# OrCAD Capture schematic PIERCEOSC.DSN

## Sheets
1 PAGE1: size A
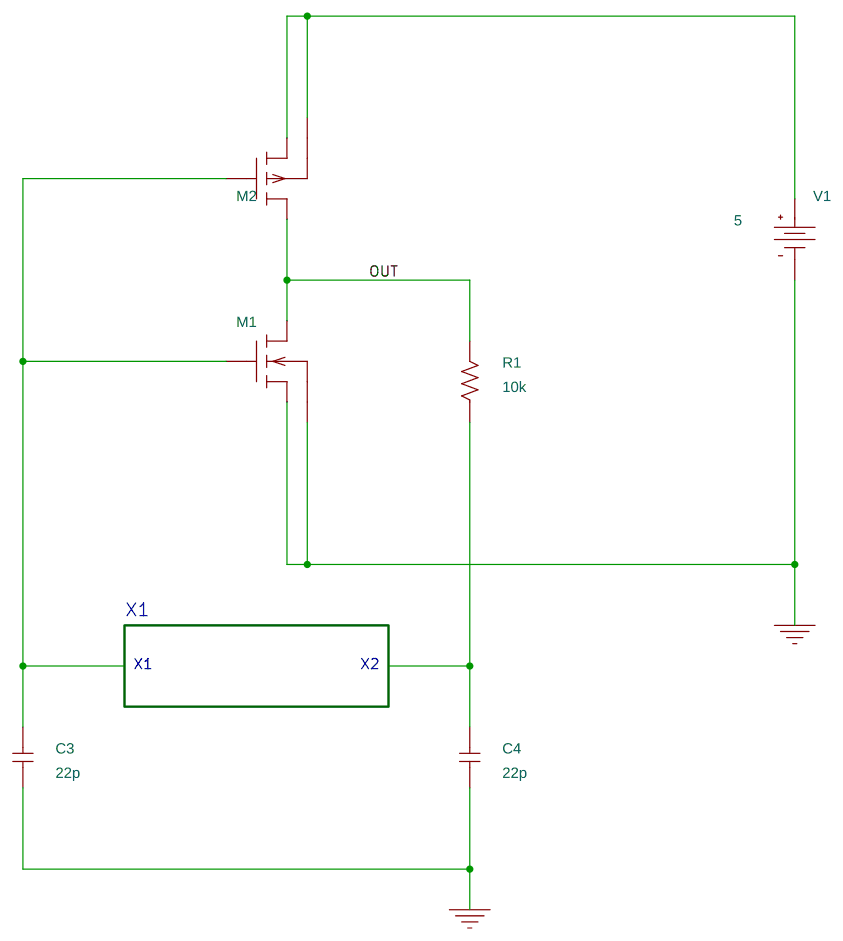
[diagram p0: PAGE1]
2 PAGE1 (2): size A; block X1
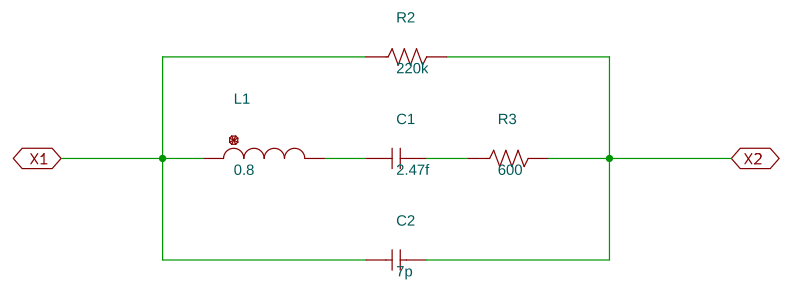
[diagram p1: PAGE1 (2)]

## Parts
sheet PAGE1 (2)
C1  2.47f  [RAD/CK05]
C2  7p  [RAD/CK05]
L1  0.8  [DISC/.350x.175/LS.200x.100/.034]
R2  220k  [AX/RC05]
R3  600  [AX/RC05]
sheet PAGE1
C3  22p  [RAD/CK05]
C4  22p  [RAD/CK05]
M1  MbreakN
M2  MbreakP
R1  10k  [AX/RC05]
V1  VDC

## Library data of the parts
C1-C4 = C
L1 = L
R1-R3 = R
M1 = MbreakN
M2 = MbreakP
V1 = VDC: DC: 5

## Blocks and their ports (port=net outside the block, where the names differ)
X1 = schematic XTAL1, on sheet PAGE1: X2=N00236, X1=N00163

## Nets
0: C3.1 C4.1 M1.0(s) M1.4(b) V1.1(-)
OUT: M1.2(d) M2.2(d) R1.2
N00107: M2.1(s) M2.4(b) V1.0(+)
N00163: C2.1 C3.2 L1.1 M1.1(g) M2.0(g) R2.1
N00236: C2.2 C4.2 R1.1 R2.2 R3.2
X1/N01485: C1.1 L1.2
X1/N01489: C1.2 R3.1
